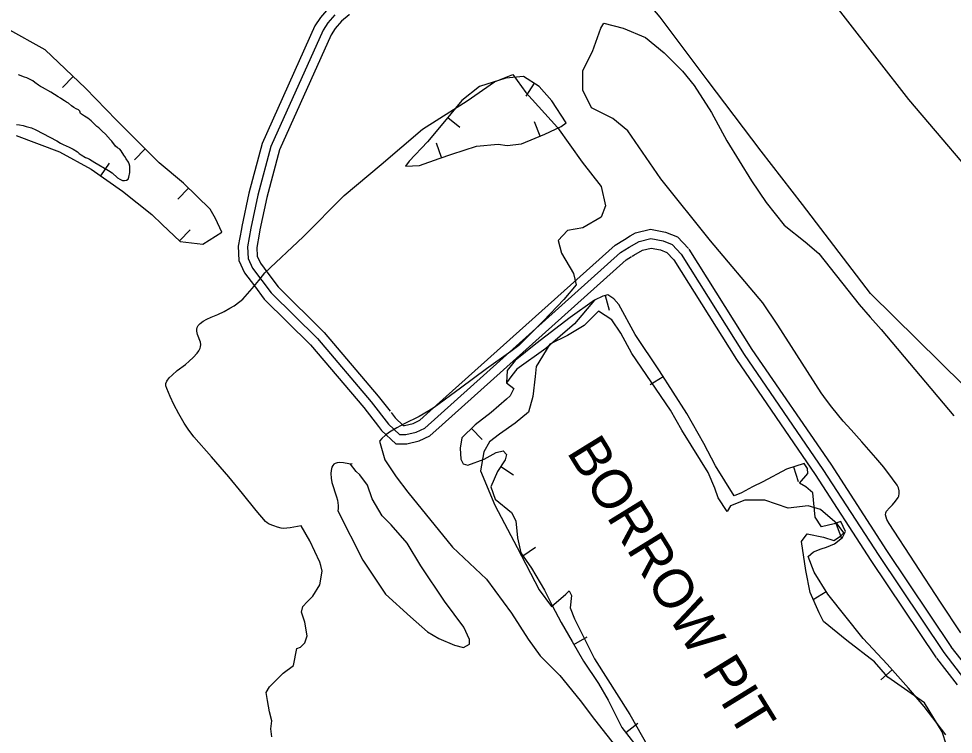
# Model space of a CAD drawing. Extents: x 3161665 to 3199565, y 885729 to 911164.
# Drawn here: x 3182991 to 3184512, y 897387 to 898552 of the extents above; entities that cross this region are included whole.
import ezdxf

# ---------------------------------------------------------------- set-up
doc = ezdxf.new("R2010")
doc.units = 0
for name, color, linetype in [('V-BORW-IDEN', 7, 'Continuous'), ('V-BORW-LINE', 7, 'Continuous'), ('V-LEVE-TOET', 7, 'Continuous'), ('V-ROAD-CNTR', 7, 'Continuous'), ('V-TOPO-SHOR', 7, 'Continuous')]:
    doc.layers.add(name, color=color, linetype=linetype)

msp = doc.modelspace()

# ---------------------------------------------------------------- linework, layer by layer
at = {"layer": 'V-BORW-LINE'}
for p, q in [((3183079.5, 898457.9), (3183062.2, 898439.7)), ((3183830, 898446.7), (3183816.7, 898425.5)), ((3183689.7, 898391.2), (3183709.1, 898375.5)), ((3183840, 898360.6), (3183830.6, 898383.8)), ((3183197, 898339.8), (3183179.3, 898322.2)), ((3183679.3, 898325.7), (3183671.2, 898349.4)), ((3183124.5, 898296), (3183138.8, 898316.5)), ((3183267.1, 898276.2), (3183249.7, 898258.2)), ((3183252.8, 898190.2), (3183270, 898208.4)), ((3183945.6, 898101.3), (3183952.1, 898077.2)), ((3184040.2, 897969.2), (3184019.1, 897955.7)), ((3183728, 897885.1), (3183745.3, 897867)), ((3183775.6, 897822.8), (3183796.6, 897809.3)), ((3184252.2, 897822.3), (3184259.9, 897798.5)), ((3184321.1, 897730.8), (3184329.7, 897707.3)), ((3183811.7, 897677.6), (3183832.2, 897691.9)), ((3184305.6, 897619.3), (3184284.4, 897606)), ((3183894.8, 897533.3), (3183916.5, 897545.7)), ((3184413, 897492.2), (3184394.3, 897475.6)), ((3183979.2, 897389.9), (3183998.9, 897405.3))]:
    msp.add_line(p, q, dxfattribs=at)
for points in [[(3183258.9, 898284.2), (3183219.3, 898317.3), (3183150.2, 898386.8), (3183099.7, 898438.6), (3183034.1, 898501), (3182971.3, 898536)], [(3183881.9, 898382.5), (3183859, 898418), (3183838.2, 898441.5), (3183812.9, 898457.5), (3183783.9, 898455.1), (3183741.1, 898441.6), (3183712.1, 898418.8), (3183684.1, 898384.4), (3183656.6, 898351.7), (3183626.8, 898320.1), (3183620.3, 898311.9), (3183643.2, 898313.1), (3183675.2, 898324.3), (3183696, 898331.5), (3183736.2, 898344.3), (3183771.5, 898347.8), (3183786, 898345.7), (3183809.6, 898348.2), (3183847.6, 898363.7), (3183873.8, 898376.6), (3183881.9, 898382.5)], [(3182987, 898361.7), (3183057.2, 898335.1), (3183108.9, 898306.8), (3183159.9, 898271.3), (3183207.8, 898232.9), (3183224.5, 898216.8), (3183254, 898189.1), (3183290.7, 898184.8), (3183321.6, 898204.4), (3183311.5, 898226.5), (3183302.5, 898241.9), (3183258.9, 898284.2)], [(3184500.2, 897386.2), (3184464.7, 897432.3), (3184439.5, 897462.2), (3184404.8, 897501.5), (3184365.7, 897542.9), (3184308.3, 897615), (3184285.7, 897651), (3184276.3, 897676.5), (3184285, 897684.3), (3184297.2, 897689.1), (3184306.1, 897692), (3184318.8, 897697), (3184332.2, 897707.6), (3184336.6, 897717.4), (3184329, 897733.7), (3184318.2, 897729.7), (3184297.9, 897724.9), (3184287.3, 897740.4), (3184283.7, 897780.4), (3184272, 897789.7), (3184261.7, 897796.1), (3184275.4, 897811.6), (3184274.9, 897819.6), (3184269.4, 897827.8), (3184240.6, 897818.6), (3184202.4, 897798.1), (3184185.7, 897789.9), (3184167.3, 897780.2), (3184155.6, 897775.5), (3184125.4, 897824), (3184106, 897860.4), (3184078.5, 897909.1), (3184034.1, 897978.8), (3183994.7, 898037.8), (3183967.6, 898086.7), (3183959.8, 898095.9), (3183949.9, 898102.5), (3183941.9, 898100.3), (3183928, 898093.9), (3183888.6, 898065.7), (3183832.6, 898022.7), (3183798.9, 897995.4), (3183786, 897979.1), (3183784.8, 897959.3), (3183796.9, 897950.2), (3183790.9, 897938.3), (3183784.9, 897932.4), (3183760, 897910.7), (3183734, 897890.8), (3183712, 897869.9), (3183709.5, 897853), (3183710.5, 897835), (3183714.2, 897827.3), (3183722.3, 897825.2), (3183748.8, 897834.9), (3183768, 897846), (3183779.7, 897848.5), (3183785.1, 897842.4), (3183782.6, 897833.7), (3183770.4, 897814.8), (3183759.3, 897789.7), (3183766.8, 897769.6), (3183793, 897748), (3183800.3, 897734.8), (3183802.8, 897706.9), (3183808.3, 897682.5), (3183825.7, 897657.5), (3183846.6, 897621.5), (3183859.1, 897596.8), (3183874.1, 897569), (3183892, 897538.2), (3183910.1, 897506.3), (3183934.5, 897469.7), (3183950.3, 897442.6), (3183972.9, 897398), (3184004.9, 897356.9)], [(3184500.2, 897386.2), (3184464.7, 897432.3), (3184439.5, 897462.2), (3184404.8, 897501.5), (3184365.7, 897542.9), (3184308.3, 897615), (3184285.7, 897651), (3184276.3, 897676.5), (3184285, 897684.3), (3184297.2, 897689.1), (3184306.1, 897692), (3184318.8, 897697), (3184332.2, 897707.6), (3184336.6, 897717.4), (3184329, 897733.7), (3184318.2, 897729.7), (3184297.9, 897724.9), (3184287.3, 897740.4), (3184283.7, 897780.4), (3184272, 897789.7), (3184261.7, 897796.1), (3184275.4, 897811.6), (3184274.9, 897819.6), (3184269.4, 897827.8), (3184240.6, 897818.6), (3184202.4, 897798.1), (3184185.7, 897789.9), (3184167.3, 897780.2), (3184155.6, 897775.5), (3184125.4, 897824), (3184106, 897860.4), (3184078.5, 897909.1), (3184034.1, 897978.8), (3183994.7, 898037.8), (3183967.6, 898086.7), (3183959.8, 898095.9), (3183949.9, 898102.5), (3183941.9, 898100.3), (3183928, 898093.9), (3183895.9, 898055.3), (3183848.9, 898014.9), (3183801.8, 897981.3), (3183793.4, 897971.3), (3183784.8, 897959.3), (3183796.9, 897950.2), (3183790.9, 897938.3), (3183784.9, 897932.4), (3183760, 897910.7), (3183734, 897890.8), (3183712, 897869.9), (3183709.5, 897853), (3183710.5, 897835), (3183714.2, 897827.3), (3183722.3, 897825.2), (3183748.8, 897834.9), (3183768, 897846), (3183779.7, 897848.5), (3183785.1, 897842.4), (3183782.6, 897833.7), (3183770.4, 897814.8), (3183759.3, 897789.7), (3183766.8, 897769.6), (3183793, 897748), (3183800.3, 897734.8), (3183802.8, 897706.9), (3183808.3, 897682.5), (3183825.7, 897657.5), (3183846.6, 897621.5), (3183859.1, 897596.8), (3183874.1, 897569), (3183892, 897538.2), (3183910.1, 897506.3), (3183934.5, 897469.7), (3183950.3, 897442.6), (3183972.9, 897398), (3184004.9, 897356.9)]]:
    msp.add_lwpolyline(points, dxfattribs=at)
at = {"layer": 'V-LEVE-TOET'}
for points in [[(3184747.1, 898061.1), (3184579.4, 898256.5), (3184440.1, 898420.5), (3184285.2, 898619.3), (3184186.5, 898717.3), (3184129.7, 898791.7), (3184104.3, 898842.4), (3184084, 898949.3), (3184035, 899217.7), (3183984.2, 899534.5), (3183936.9, 899881.1), (3183904.9, 900117.8), (3183885.2, 900211.3), (3183873.7, 900264.9), (3183860.2, 900326.2)], [(3184377.4, 898104.4), (3184266.8, 898249.5), (3184199.5, 898336.4), (3184111.6, 898452.3), (3184035.2, 898554.1), (3183962.5, 898640.6), (3183918.2, 898691), (3183897, 898726.7), (3183869.2, 898835.7)], [(3185718, 896416.3), (3185711.8, 896427.6), (3185710, 896443), (3185708.8, 896477.8), (3185706.9, 896486.4), (3185702.6, 896496.5), (3185610.3, 896616.4), (3185505.7, 896750.6), (3185380.6, 896899.6), (3185184.5, 897151.7), (3185009.6, 897360), (3184774.3, 897657.1), (3184658.1, 897805.3), (3184529, 897955.3), (3184377.4, 898104.4)]]:
    msp.add_lwpolyline(points, dxfattribs=at)
at = {"layer": 'V-ROAD-CNTR'}
for points in [[(3183504.3, 898576.8), (3183495.1, 898568.9), (3183482.4, 898554), (3183473.1, 898540.4), (3183387.2, 898348.6), (3183365.4, 898268.1), (3183354.3, 898213.9), (3183353.6, 898210.1)], [(3183505.7, 898558.3), (3183494.3, 898545), (3183486.3, 898533.1), (3183401.3, 898343.6), (3183380, 898264.6), (3183369, 898211), (3183363.4, 898180.4), (3183364.2, 898161.8), (3183371.3, 898146), (3183401.8, 898105.5), (3183477.1, 898031.1), (3183564.5, 897928.2), (3183592.8, 897891.9), (3183610.9, 897874.9), (3183621.1, 897875), (3183637.7, 897879), (3183652, 897885.6), (3183970.8, 898171.2), (3183984.6, 898179.8), (3184000.8, 898189.1), (3184020, 898193.9), (3184039.8, 898190.2), (3184054.9, 898184.1), (3184069.3, 898168.7), (3184171.8, 898005.5), (3184300.2, 897818.3), (3184390.9, 897678.1), (3184496.7, 897520.2)], [(3183529.4, 898558.9), (3183528.9, 898558.3), (3183516.3, 898547.7), (3183506.3, 898535.9), (3183499.4, 898525.8), (3183415.5, 898338.5), (3183394.6, 898261.1), (3183383.7, 898208.1), (3183382.4, 898200.9)], [(3183353.6, 898210.1), (3183348.4, 898181.5), (3183349.4, 898158.3), (3183358.3, 898138.4), (3183374.5, 898116.8)], [(3183986.4, 898198.2), (3183995.2, 898203.2), (3184019.5, 898209.2), (3184044, 898204.6), (3184063.6, 898196.8), (3184081.3, 898177.9)], [(3183382.4, 898200.9), (3183378.5, 898179.4), (3183379.1, 898165.3), (3183384.3, 898153.7), (3183396.5, 898137.5)], [(3183660.5, 897913.4), (3183961.8, 898183.2), (3183976.9, 898192.7), (3183986.4, 898198.2)], [(3183989.5, 898165.2), (3183992.3, 898167), (3184006.5, 898175.1), (3184020.4, 898178.5), (3184035.6, 898175.7), (3184046.2, 898171.4), (3184057.1, 898159.8)], [(3184081.9, 898177), (3184184.3, 898013.7), (3184312.7, 897826.6), (3184403.4, 897686.4), (3184509.2, 897528.5)], [(3183680, 897890.6), (3183979.9, 898159.2), (3183988.6, 898164.7)], [(3184057.1, 898159.8), (3184057.4, 898159.5), (3184159.2, 897997.3), (3184287.7, 897809.9), (3184378.3, 897669.9), (3184484.2, 897511.8)], [(3183396.5, 898137.5), (3183413.1, 898115.4), (3183488.1, 898041.3), (3183576.2, 897937.7), (3183595.4, 897912.9)], [(3183374.5, 898116.8), (3183390.4, 898095.6), (3183466.1, 898020.9), (3183552.9, 897918.8), (3183576.8, 897888)], [(3183597.1, 897910.8), (3183603.9, 897902.1), (3183616.8, 897889.9), (3183619.2, 897890), (3183632.8, 897893.2), (3183643.7, 897898.3), (3183660.5, 897913.4)], [(3183576.8, 897888), (3183581.7, 897881.8), (3183605, 897859.8), (3183623, 897860), (3183642.7, 897864.8), (3183660.4, 897873), (3183680, 897890.6)], [(3184496.7, 897520.2), (3184530.8, 897476.6)], [(3184508.5, 897529.4), (3184542.8, 897485.6), (3184568.1, 897449.5), (3184581.7, 897431), (3184593.4, 897414.3), (3184598.3, 897408.8), (3184607.7, 897401), (3184626.8, 897385.6), (3184646.1, 897366.1), (3184658.1, 897341.1), (3184678.8, 897301.4), (3184687.3, 897284.2), (3184699.7, 897255.5), (3184725.7, 897214.5), (3184775.1, 897147), (3184845.1, 897060.1), (3184886.8, 897005.2), (3184944.3, 896929.2), (3185057.1, 896775.1), (3185244.3, 896509.1), (3185438.6, 896252.6), (3185453.6, 896232.5)], [(3184484.9, 897510.9), (3184518.7, 897467.7)]]:
    msp.add_lwpolyline(points, dxfattribs=at)
at = {"layer": 'V-TOPO-SHOR'}
for points in [[(3184202.3, 898089.5), (3184117.3, 898190.3), (3184036.3, 898291.3), (3183982.5, 898369.6), (3183958.2, 898389.6), (3183923.6, 898406.6), (3183909, 898435.7), (3183909.4, 898467.5), (3183924.8, 898498.2), (3183938.4, 898536.3), (3183943.6, 898544.8), (3183975, 898536.3), (3184011.2, 898521.1), (3184041.6, 898496.4), (3184071.5, 898466.3), (3184090.5, 898443), (3184118.7, 898399.1), (3184143.6, 898353.2), (3184183.6, 898288), (3184207.7, 898252.8), (3184236.9, 898215.8), (3184271.1, 898188.7), (3184293.5, 898169.9), (3184359.3, 898086.7)], [(3183090.3, 898401.3), (3183088.5, 898403.3), (3183084.7, 898405.1), (3183080.9, 898407.5), (3183076.7, 898409.9), (3183071.7, 898414.1), (3183068.5, 898416.1), (3183065.5, 898418.3), (3183062.6, 898419.9), (3183058.8, 898422.7), (3183055, 898424.9), (3183043, 898432.5), (3183029.9, 898440), (3183026.5, 898441.6), (3183022.9, 898443.6), (3183017.3, 898448.2), (3183013.9, 898450.6), (3183008.3, 898453.6), (3183003.9, 898455.6), (3183000.5, 898456.6), (3182990.6, 898460.6)], [(3183391.5, 898138.4), (3183454.2, 898196.9), (3183520.6, 898264.1), (3183580.8, 898314.4), (3183648.3, 898372), (3183721.1, 898417.9), (3183765.5, 898449), (3183795.3, 898460.8), (3183816.2, 898431.9), (3183867.9, 898374.6), (3183908.2, 898318.4), (3183939.3, 898278.5), (3183946.1, 898247.4), (3183939.3, 898228.6), (3183909.2, 898211.3), (3183884.1, 898207.3), (3183869.1, 898190.7), (3183874.5, 898170), (3183894, 898137.4), (3183898.6, 898118.5), (3183878.5, 898094.6)], [(3183155.7, 898339.3), (3183151.5, 898341.7), (3183148.7, 898344.5), (3183142.5, 898352.5), (3183140.1, 898354.9), (3183132.1, 898363.7), (3183127, 898368.6), (3183123.8, 898371.4), (3183121.2, 898374), (3183118.2, 898376.4), (3183108.8, 898385.6), (3183103.4, 898390.2), (3183097.8, 898393.4), (3183091.7, 898397.8), (3183090.3, 898401.3)], [(3182987.2, 898379.8), (3182992, 898379), (3182997.9, 898377.8), (3183003.3, 898376.6), (3183011.5, 898374.2), (3183018.9, 898371.2), (3183053, 898353.1), (3183059, 898349.5), (3183063.5, 898347.3), (3183073.1, 898342.9), (3183079.5, 898339.5), (3183086.5, 898335.1), (3183089.1, 898332.2), (3183092.7, 898330.2), (3183099.4, 898326), (3183102.8, 898324.6), (3183106, 898323), (3183115, 898318), (3183137.3, 898304.8), (3183143.3, 898300.8), (3183151.9, 898293.1), (3183155.5, 898290.9), (3183159.7, 898288.7), (3183163, 898288.7), (3183166.2, 898289.3), (3183169, 898290.7), (3183170.2, 898294.1), (3183171.6, 898301.6), (3183171.6, 898311.8), (3183170.8, 898315.6), (3183169.4, 898318.6), (3183165.8, 898323.6), (3183163.8, 898327.4), (3183161.9, 898330), (3183157.7, 898336.9), (3183155.7, 898339.3)], [(3183351, 898091.7), (3183355.5, 898095.6), (3183359.7, 898099.9), (3183371, 898112.8), (3183381.7, 898125.9), (3183391.5, 898138.4)], [(3183450.6, 897726.7), (3183432.9, 897723.4), (3183427.6, 897722.6), (3183422.3, 897722.3), (3183418.2, 897722.7), (3183412.1, 897724.2), (3183406, 897726.4), (3183398.8, 897729.3), (3183395.5, 897731.1), (3183392.7, 897733.6), (3183377.2, 897751.5), (3183355.2, 897778.9), (3183333.1, 897806), (3183304.5, 897838.6), (3183276.2, 897871.5), (3183266.9, 897883.8), (3183260.5, 897893.5), (3183251.7, 897908.5), (3183243.3, 897923.8), (3183237.3, 897936.7), (3183232, 897949.9), (3183230.6, 897954.1), (3183230.2, 897956.2), (3183230.4, 897958.3), (3183232.1, 897962), (3183236, 897967.1), (3183240.7, 897971.7), (3183249.1, 897979.1), (3183262.2, 897989.3), (3183268.6, 897994.6), (3183274.8, 898000.2), (3183281.2, 898007.3), (3183283.9, 898011.2), (3183286.2, 898015.4), (3183287, 898017.9), (3183287.3, 898021.8), (3183286.7, 898025.6), (3183282.2, 898037.6), (3183281, 898043.4), (3183280.9, 898046.3), (3183281.4, 898049.2), (3183283.2, 898052.7), (3183286.1, 898055.7), (3183291.3, 898059.7), (3183296.9, 898062.9), (3183304, 898066.2), (3183314.9, 898070.5), (3183325.6, 898075.3), (3183334.7, 898080.6), (3183341.5, 898084.7), (3183351, 898091.7)], [(3183878.5, 898094.6), (3183845.2, 898060.3), (3183811.6, 898026.4), (3183804.8, 898020.2), (3183792.3, 898010), (3183752.5, 897981.9), (3183709.9, 897950.4), (3183667, 897919.3), (3183658.4, 897913.5), (3183642.7, 897904.5), (3183618.3, 897892.2), (3183606.3, 897885.8), (3183594.6, 897878.7), (3183588.2, 897873.9), (3183582.2, 897868.6), (3183578.3, 897864.4)], [(3184524.4, 897552.2), (3184491.3, 897602.1), (3184407.8, 897730.2), (3184404.3, 897737), (3184402.2, 897744.2), (3184402.3, 897747.4), (3184403.8, 897750.5), (3184408.5, 897755.9), (3184413.3, 897760.8), (3184418, 897766.4), (3184422.4, 897772.4), (3184423.6, 897775), (3184424.3, 897779.2), (3184424.1, 897783.4), (3184423, 897788.1), (3184420.8, 897792.7), (3184413.5, 897803.1), (3184399.3, 897821.8), (3184386.3, 897837.3), (3184363.2, 897863.3), (3184345.8, 897882.5), (3184333, 897897), (3184314.5, 897919.4), (3184305.8, 897931), (3184297.5, 897943.1), (3184226.5, 898053.2), (3184202.3, 898089.5)], [(3184359.3, 898086.7), (3184377, 898066.2), (3184395, 898045.8), (3184513, 897905.4)], [(3184501.3, 897369.5), (3184494.1, 897391.2), (3184465.3, 897438.3), (3184405.7, 897480), (3184384.1, 897505.3), (3184338.9, 897539.8), (3184301, 897570.6), (3184293.8, 897585.1), (3184279.4, 897617.7), (3184272.3, 897653.9), (3184265.1, 897700.9), (3184274.2, 897713.6), (3184301.3, 897708.1), (3184317.6, 897702.6), (3184328.5, 897709.8), (3184333.9, 897715.2), (3184323.1, 897729.7), (3184296, 897753.3), (3184276.1, 897758.8), (3184243.6, 897755.2), (3184205.6, 897768), (3184173, 897768), (3184149.5, 897759.1), (3184144.1, 897750), (3184129.7, 897771.8), (3184124.3, 897788), (3184113.5, 897813.4), (3184100.8, 897833.3), (3184070.2, 897882.2), (3184052.2, 897914.8), (3183989.1, 898007.2), (3183971.1, 898039.8), (3183956.7, 898061.5), (3183935, 898076), (3183911.4, 898052.6), (3183884.3, 898036.3), (3183855.3, 898021.9), (3183833.5, 897985.8), (3183831.7, 897969.5), (3183828, 897937), (3183820.7, 897911.7), (3183799, 897893.7), (3183773.6, 897875.6), (3183757.3, 897863), (3183748.2, 897846.7), (3183742.7, 897816), (3183766.1, 897759.9), (3183802.1, 897691.1), (3183838.2, 897622.3), (3183858, 897595.1), (3183881.5, 897615), (3183887, 897620.4), (3183890.6, 897613.1), (3183888.7, 897593.2), (3183895.9, 897575.1), (3183928.3, 897510), (3183986, 897419.4), (3184061.7, 897285.4)], [(3183578.3, 897864.4), (3183586.7, 897834), (3183605.1, 897806.3), (3183624.4, 897781.4), (3183697.1, 897691.7), (3183752.4, 897639.9), (3183792.9, 897584.4), (3183820.4, 897541.9), (3183839.8, 897515.1), (3183872, 897482.7), (3183905.1, 897442), (3183928.1, 897411.5), (3183982.4, 897342.2)], [(3183533.8, 897827.4), (3183531.1, 897826.9), (3183528.2, 897827.1), (3183519.4, 897828.9), (3183512.6, 897829.4), (3183509.2, 897829), (3183505.8, 897828), (3183504.1, 897827), (3183502.2, 897824.8), (3183500.8, 897822.1), (3183499.3, 897816.7), (3183498.8, 897811.4), (3183499.3, 897803.8), (3183500.6, 897797.1), (3183508.3, 897773.8), (3183509.8, 897768), (3183511, 897759.3), (3183511, 897754.9), (3183510.3, 897750.6)], [(3183510.3, 897750.6), (3183551.2, 897670.8), (3183588, 897615.3), (3183628.6, 897578.3), (3183656.2, 897554.2), (3183674.6, 897543.1), (3183700.5, 897532), (3183715.2, 897528.3), (3183724.5, 897533.8), (3183724.5, 897541.2), (3183715.3, 897561.5), (3183684, 897604), (3183645.4, 897661.3), (3183623.3, 897698.3), (3183597.5, 897727.9), (3183582.8, 897742.7), (3183566.2, 897770.4), (3183558.9, 897792.6), (3183546, 897809.2), (3183540.5, 897814.8), (3183531.1, 897826.9)], [(3183403, 897383.1), (3183401.1, 897396.1), (3183403, 897409), (3183399.3, 897423.8), (3183395.7, 897442.2), (3183393.9, 897455.2), (3183399.4, 897464.4), (3183421.6, 897486.5), (3183438.3, 897499.4), (3183443.9, 897527), (3183449.4, 897528.9), (3183456.8, 897536.2), (3183460.5, 897547.3), (3183456.9, 897569.5), (3183451.4, 897586.1), (3183453.3, 897595.3), (3183460.7, 897602.7), (3183469.9, 897611.9), (3183481, 897630.3), (3183484.8, 897652.5), (3183482.9, 897661.7), (3183481.1, 897667.2), (3183464.6, 897702.3), (3183450.6, 897726.7)]]:
    msp.add_lwpolyline(points, dxfattribs=at)

# ---------------------------------------------------------------- texts
at = {"layer": 'V-BORW-IDEN'}
msp.add_text('BORROW PIT', height=64, rotation=301.6483, dxfattribs=at).set_placement((3183882.1, 897846.5))

doc.saveas('drawing.dxf')
